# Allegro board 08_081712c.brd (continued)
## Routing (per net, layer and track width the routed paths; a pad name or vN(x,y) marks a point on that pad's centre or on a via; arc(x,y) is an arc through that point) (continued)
_N2537: length 3.2
  BOTTOM w0.305: R591.1 105.91,58.5 105.61,58.81 U77.4
_N2538: length 3.2
  BOTTOM w0.305: R592.1 97.91,59.31 U77.8
_N2539: length 3
  BOTTOM w0.305: U77.3 106.49,59.31 C416.1
_N2540: length 7.2
  BOTTOM w0.305: U77.6 100.38,56.81 R593.1 99.83,56.26 96.52,56.26 R594.1 95,56.13 C419.1
_N2565: length 3.5
  BOTTOM w0.305: C424.1 225.3,58.5 225.6,58.81 U78.7
_N2567: length 3.2
  BOTTOM w0.305: U78.4 232.61,58.81 232.91,58.5 R595.1
_N2568: length 3.2
  BOTTOM w0.305: U78.8 224.91,59.31 R596.1
_N2569: length 3
  BOTTOM w0.305: U78.3 233.49,59.31 C422.1
_N2570: length 7.2
  BOTTOM w0.305: U78.6 227.38,56.81 R597.1 226.83,56.26 223.52,56.26 R598.1 222,56.13 C425.1
_N2633: length 1
  BOTTOM w0.114: R599.1 208.5,23.57 v2(207.84,22.91)
_N2642: length 9.5
  BOTTOM w0.127: PB1.3 173.24,23.24 166.76,23.24 R9.1
_N2684: length 87.7
  TOP w0.127: v1(188.85,76.32) 190.23,76.32 191.34,75.21 191.34,66.9 183.97,59.54 183.97,28.14 165.89,10.06 v1(165.89,3.49)
  BOTTOM w0.127: R600.1 v1(188.85,76.32) ; PB1.5 v1(165.89,3.49)
_N2688: length 95.2
  TOP w0.127: v1(152.18,3.49) 158,3.49 183.04,28.53 183.04,59.59 190.91,67.46 190.91,74.7 v1(189.99,75.62)
  BOTTOM w0.127: PB2.5 v1(152.18,3.49) ; R601.1 v1(189.99,75.62)
_N2692: length 183.3
  TOP w0.127: v1(184.84,32.49) 184.84,59.33 192.96,67.46 192.96,74.5 v1(191.13,76.32) ; v1(234.19,16.74) 246.05,16.74 252.02,10.77 285.62,10.77 v1(292.89,3.49)
  L8_SIG w0.127: v1(234.19,16.74) 217.65,16.74 211.84,10.92 203.41,10.92 202.93,11.4 202.48,11.4 202,10.92 193.47,10.92 186.51,17.88 186.51,30.79 184.84,32.47 v1(184.84,32.49)
  BOTTOM w0.127: R602.1 v1(191.13,76.32) ; PB3.5 v1(292.89,3.49)
_N2696: length 169.2
  TOP w0.127: v1(279.18,3.49) 272.53,10.13 251.43,10.13 245.39,16.18 v1(235.08,16.18) ; v1(192.28,76.32) 192.28,76.32 193.77,74.83 193.77,67.12 185.64,59 v1(185.64,30.89)
  L8_SIG w0.127: v1(235.08,16.18) 218.11,16.18 212.24,10.31 193.29,10.31 185.64,17.96 v1(185.64,30.89)
  BOTTOM w0.127: R603.1 v1(192.28,76.32) ; PB4.5 v1(279.18,3.49)
_N2698: length 9.8
  BOTTOM w0.127: S14.3 248.64,25.51 C383.1 248.66,25.54 U64.1 244.33,25.54 244.03,25.84 R546.2
`: length 386.4
  TOP w0.14: J1.T1 27.3,14.9 R567.1 27.3,16.29 R566.2 v1(26.07,16.3) ; J2.T1 394.97,14.9 R572.1 394.96,16.29 R571.2 v1(393.74,16.3)
  L3_SIG w0.127: v1(26.07,16.3) 52.9,16.3 56.13,19.53 91.49,19.53 100.3,10.72 198.58,10.72 199.08,10.21 208.79,10.21 209.3,10.72 315.53,10.72 317.13,12.32 368.53,12.32 373.58,17.37 392.66,17.37 v1(393.74,16.3)
A0N_FB: length 15.6
  TOP w0.508: 328.85,146.94 329.56,146.23 R174.1 ; 328.85,146.94 U22.7 325.18,146.94 R170.2 323.24,146.62 C118.2 ; 328.85,146.94 329.56,147.65 329.56,152.26 S3.3
A1N_FB: length 15.6
  TOP w0.508: C120.2 304.19,146.62 R172.2 306.13,146.94 U23.7 309.8,146.94 ; 309.8,146.94 310.52,146.23 R176.1 ; 309.8,146.94 310.52,147.65 310.52,152.26 S4.3
A2B1_IO1: length 67.4
  TOP w0.127: DS7.A v1(24.51,105.12) 25.31,105.92 26.94,105.92 29.73,108.7 U8.14
  BOTTOM w0.127: J4.52 23.3,74.2 24.03,74.93 25.4,74.93 26.04,75.56 39.37,75.56 40.01,76.2 40.01,93.6 30.23,103.38 27.81,103.38 26.67,104.52 25.11,104.52 v1(24.51,105.12)
A2B1_IO2: length 64.7
  TOP w0.127: U8.15 30.23,108.5 26.85,105.12 v1(26.04,105.12) DS8.A
  BOTTOM w0.127: v1(26.04,105.12) 26.71,105.12 28.07,103.76 30.35,103.76 40.36,93.75 40.36,76.05 39.52,75.21 26.18,75.21 25.53,74.55 24.77,74.55 24.57,74.36 J4.48
A2B1_IO7: length 61.8
  TOP w0.127: DS9.A v1(27.56,105.12) 30.73,108.29 U8.16
  BOTTOM w0.127: J4.44 25.84,74.28 26.42,74.85 39.67,74.85 40.72,75.9 40.72,93.9 30.48,104.14 28.54,104.14 v1(27.56,105.12)
A2B1_IRQ: length 186.7
  TOP w0.127: SOMA.227 v1(170.65,64.78)
  BOTTOM w0.127: J4.60 20.76,62.83 49.13,34.47 103.61,34.47 126.77,57.63 164.44,57.63 170.65,63.84 v1(170.65,64.78)
A2B1_RESET: length 184.5
  TOP w0.127: SOMA.225 v1(170.14,64.27)
  BOTTOM w0.127: J4.56 22.03,62.24 49.25,35.03 103.58,35.03 126.54,57.99 163.86,57.99 v1(170.14,64.27)
A2B2_IO1: length 74.1
  TOP w0.127: U8.17 31.23,108.07 29.08,105.92 v1(29.08,105.12) DS10.A
  BOTTOM w0.127: J5.52 76.01,74.23 75.44,74.8 60.2,74.8 58.17,76.83 58.17,84.38 48.54,94 41.12,94 30.61,104.52 29.68,104.52 v1(29.08,105.12)
A2B2_IO2: length 73.6
  TOP w0.127: DS11.A v1(30.61,105.12) 30.61,106.55 31.73,107.68 U8.18
  BOTTOM w0.127: v1(30.61,105.12) 30.61,105.03 41.27,94.36 48.69,94.36 58.53,84.52 58.53,76.98 60.35,75.16 76.48,75.16 77.28,74.36 J5.48
A2B2_IO7: length 66.3
  TOP w0.127: DS12.A v1(32.13,105.12)
  BOTTOM w0.127: v1(32.13,105.12) 32.13,104.01 41.42,94.72 48.84,94.72 58.88,84.67 58.88,77.13 60.5,75.52 77.26,75.52 78.55,74.23 J5.44
A2B2_IRQ: length 111.4
  TOP w0.127: SOMA.233 v1(172.14,64.27)
  L8_SIG w0.127: v1(172.14,64.27) 172.14,63.28 169.57,60.71 126.06,60.71 121.36,65.41 112.4,65.41 111.99,65.81 77.57,65.81 76.71,66.67 74.12,66.67 v1(73.47,67.32)
  BOTTOM w0.127: J5.60 v1(73.47,67.32)
A2B2_RESET: length 109.2
  TOP w0.127: SOMA.231 v1(171.65,64.78)
  L8_SIG w0.127: v1(171.65,64.78) 171.65,63.49 169.23,61.07 126.4,61.07 121.64,65.83 112.68,65.83 112.34,66.17 78.11,66.17 76.95,67.32 v1(74.74,67.32)
  BOTTOM w0.127: J5.56 v1(74.74,67.32)
A2B3_IO1: length 127.1
  TOP w0.127: DS13.A v1(252.48,110.2) 253.28,111 254.91,111 257.69,113.78 U51.14
  L8_SIG w0.127: v1(338.65,75.69) 329.03,75.69 327.79,76.93 322.86,76.93 321.06,78.74 321.06,86.96 321.94,87.85 321.94,90.04 318.26,93.73 318.26,102.4 312.86,107.8 254.88,107.8 v1(252.48,110.2)
  BOTTOM w0.127: P3.52 v1(338.65,75.69)
A2B3_IO2: length 126.2
  TOP w0.127: U51.15 258.2,113.58 254.82,110.2 v1(254,110.2) DS14.A
  L8_SIG w0.127: v1(254,110.2) 256.02,108.18 312.98,108.18 318.64,102.52 318.64,93.85 323.47,89.03 323.47,82.3 322.07,80.9 322.07,78.49 323.27,77.29 327.94,77.29 328.92,76.31 339.3,76.31 v1(339.92,75.69)
  BOTTOM w0.127: P3.48 v1(339.92,75.69)
A2B3_IO7: length 121
  TOP w0.127: DS15.A v1(255.52,110.2) 258.69,113.37 U51.16
  L8_SIG w0.127: v1(341.19,75.69) 340.04,76.83 329.26,76.83 326.14,79.96 326.14,86.87 319,94.01 319,102.67 313.11,108.56 257.16,108.56 v1(255.52,110.2)
  BOTTOM w0.127: P3.44 v1(341.19,75.69)
A2B3_IRQ: length 55.4
  TOP w0.127: SOMB.227 297.65,64.35 296.98,63.69 v1(296.98,61.71)
  L8_SIG w0.127: v1(296.98,61.71) 317.3,61.71 318.74,60.27 332.43,60.27 335.92,63.75 335.92,70.99 336.11,71.18 v1(336.11,71.72)
  BOTTOM w0.14: P3.60 v1(336.11,71.72)
A2B3_RESET: length 57.5
  TOP w0.127: v1(296.43,61.14) 296.43,63.77 297.14,64.48 SOMB.225
  L8_SIG w0.127: v1(296.43,61.14) 317.37,61.14 318.59,59.91 332.78,59.91 336.55,63.68 336.55,70.9 v1(337.38,71.72)
  BOTTOM w0.14: P3.56 v1(337.38,71.72)
A2B4_IO1: length 170.6
  TOP w0.127: U51.17 259.2,113.15 257.05,111 v1(257.05,110.2) DS16.A
  L8_SIG w0.127: v1(391.35,75.64) 390.41,76.58 375.72,76.58 368.86,83.44 361.32,83.44 360.17,82.3 333.88,82.3 333.6,82.58 333.6,86.82 331.91,88.52 326,88.52 320.07,94.45 320.07,103.11 312.8,110.38 305.27,110.38 304.53,109.64 301.28,109.64 300.51,110.41 298.88,110.41 298.12,109.65 262.43,109.65 260.93,111.15 258,111.15 v1(257.05,110.2)
  BOTTOM w0.127: P4.52 v1(391.35,75.64)
A2B4_IO2: length 166.8
  TOP w0.127: U51.18 259.69,112.76 258.57,111.63 v1(258.57,110.2) DS17.A
  L8_SIG w0.127: v1(392.62,74.73) 391.49,74.73 390.15,76.07 375.39,76.07 370.56,80.9 360.93,80.9 360.11,81.72 332.04,81.72 331.06,82.7 331.06,86.82 330,87.88 326.13,87.88 319.71,94.31 319.71,102.96 313.39,109.28 262.3,109.28 262.27,109.31 261.89,109.31 260.45,110.74 259.12,110.74 v1(258.57,110.2)
  BOTTOM w0.127: P4.48 v1(392.62,74.73)
A2B4_IO7: length 158.9
  TOP w0.127: DS18.A v1(260.1,110.2)
  L8_SIG w0.127: v1(260.1,110.2) 261.38,108.92 313.25,108.92 319.35,102.81 319.35,94.16 326.03,87.48 327.87,87.48 328.68,86.67 328.68,82.17 329.48,81.37 359.83,81.37 362.71,78.49 372.06,78.49 374.98,75.56 389.89,75.56 391.27,74.18 393.51,74.18 v1(393.89,74.56)
  BOTTOM w0.127: P4.44 v1(393.89,74.56)
A2B4_IRQ: length 107.3
  TOP w0.127: SOMB.233 299.14,63.94 298.66,63.46 v1(298.66,60.59)
  L8_SIG w0.127: v1(388.81,71.72) 388.81,70.07 387.86,69.12 375.61,69.12 371.6,73.13 360.63,73.13 351.04,63.53 337.4,63.53 333.42,59.56 317.68,59.56 316.65,60.59 v1(298.66,60.59)
  BOTTOM w0.127: P4.60 v1(388.81,71.72)
A2B4_RESET: length 109.1
  TOP w0.127: SOMB.231 298.65,64.08 297.81,63.25 v1(297.81,60.05)
  L8_SIG w0.127: v1(297.81,60.05) 316.15,60.05 317.37,58.83 333.4,58.83 337.57,62.99 352.6,62.99 360.2,70.59 372.01,70.59 374.37,68.22 388.23,68.22 390.08,70.07 v1(390.08,71.72)
  BOTTOM w0.127: P4.56 v1(390.08,71.72)
A2N_FB: length 15.6
  TOP w0.508: S5.3 289.94,152.26 289.94,147.65 289.23,146.94 ; 289.23,146.94 289.94,146.23 R202.1 ; 289.23,146.94 U24.7 285.56,146.94 R198.2 283.61,146.62 C132.2
A3N_FB: length 15.6
  TOP w0.508: R204.1 270.89,146.23 270.18,146.94 ; C134.2 264.56,146.62 R200.2 266.51,146.94 U25.7 270.18,146.94 ; 270.18,146.94 270.89,147.65 270.89,152.26 S6.3
A4N_FB: length 15.6
  TOP w0.508: 251.13,146.94 251.84,147.65 251.84,152.26 S7.3 ; 251.13,146.94 U26.7 247.46,146.94 R226.2 245.51,146.62 C146.2 ; 251.13,146.94 251.84,146.23 R230.1
A5N_FB: length 15.6
  TOP w0.508: C148.2 226.46,146.62 R228.2 228.41,146.94 U27.7 232.08,146.94 ; R232.1 232.79,146.23 232.08,146.94 ; 232.08,146.94 232.79,147.65 232.79,152.26 S8.3
A6N_FB: length 15.6
  TOP w0.508: S9.3 212.22,152.26 212.22,147.65 211.5,146.94 ; C160.2 205.89,146.62 R254.2 207.83,146.94 U28.7 211.5,146.94 ; R258.1 212.22,146.23 211.5,146.94
A7N_FB: length 15.6
  TOP w0.508: 192.45,146.94 193.17,147.65 193.17,152.26 S10.3 ; 192.45,146.94 193.17,146.23 R260.1 ; 192.45,146.94 U29.7 188.78,146.94 R256.2 186.84,146.62 C162.2
ADAU1966A_RESET_SOM_A*: length 114
  TOP w0.127: U8.6 v1(29.23,117.32)
  L3_SIG w0.127: v1(29.23,117.32) 30.01,116.54 42.75,116.54 58.86,100.42 130.95,100.42 v1(133.21,98.16)
  BOTTOM w0.14: U39.10 v1(133.21,98.16)
ADAU1966A_RESET_SOM_B*: length 141.9
  TOP w0.127: U51.6 257.2,122.02 256.94,122.28 v1(256.46,122.28)
  L8_SIG w0.127: v1(256.46,122.28) 250.44,122.28 238.68,110.52 227.58,110.52 226.95,109.88 224.61,109.88 223.11,111.38 201.45,111.38 201.04,111.79 167.18,111.79 162.23,106.83 136.8,106.83 135.36,105.38 v1(133.83,105.38)
  BOTTOM w0.127: U39.11 133.5,97.66 133.83,97.99 v1(133.83,105.38)
ADAU1979_A_RESET_SOM_A*: length 310.2
  TOP w0.127: v1(308.09,101.35) 308.09,99.81 306.78,98.5 296.19,98.5 293.42,101.27 293.42,102.11 290.96,104.57 269.88,104.57 268.58,103.28 237.57,103.28 234.26,99.97 201.37,99.97 198.35,96.95 175.16,96.95 167.03,105.08 143.94,105.08 131.95,93.09 99.75,93.09 94.74,98.09 62.69,98.09 40.74,120.04 30.68,120.04 29.72,119.08 29.72,116.25 U8.5
  BOTTOM w0.14: U35.10 v1(308.09,101.35)
ADAU1979_A_RESET_SOM_B*: length 89.3
  TOP w0.127: v1(256.67,123.06) 257.34,123.06 257.69,122.71 U51.5
  L8_SIG w0.127: v1(306.34,101.85) 307.71,100.48 310.06,100.48 310.62,101.04 310.62,105 308.99,106.63 307.11,106.63 306.65,107.09 254.08,107.09 251.69,109.47 251.69,111.58 257.1,116.99 257.1,122.63 v1(256.67,123.06)
  BOTTOM w0.14: U35.11 v1(306.34,101.85)
ADAU1979_B_RESET_SOM_A*: length 215.3
  TOP w0.127: U8.4 v1(30.23,117.32)
  L3_SIG w0.127: v1(230.37,101.35) 227.02,104.7 202.11,104.7 194.44,97.04 135.37,97.04 131.48,100.93 59.47,100.93 42.82,117.58 31.26,117.58 31,117.32 v1(30.23,117.32)
  BOTTOM w0.14: U37.10 v1(230.37,101.35)
ADAU1979_B_RESET_SOM_B*: length 41.5
  TOP w0.127: U51.4 258.2,123.19 v1(257.84,123.55)
  BOTTOM w0.127: U37.11 230.58,101.85 231.14,102.41 231.14,103 231.9,103.76 231.9,105.41 232.92,106.43 232.92,107.16 249.3,123.55 v1(257.84,123.55)
ADAU_CLK: length 12.8
  TOP w0.14: v1(308.09,102.35) 307.59,101.86 307.59,100.97 306.71,100.08 305.94,100.08 305.56,100.46 305.56,106.17 306.32,106.93 R123.1
  BOTTOM w0.14: U35.12 v1(308.09,102.35)
ADAU_CLK2: length 11.8
  TOP w0.14: v1(230.37,102.35) 229.87,101.86 229.87,101.44 228.81,100.38 228.42,100.38 228.14,100.66 228.14,106.47 228.6,106.93 R582.1
  BOTTOM w0.14: U37.12 v1(230.37,102.35)
ADC1_BCLK: length 9
  TOP w0.14: U20.5 302.3,103.45 v1(301.7,102.85)
  BOTTOM w0.14: U34.4 v1(301.7,102.85)
ADC1_LRCLK: length 11.4
  TOP w0.14: v1(299.7,101.35) 300.74,102.39 300.74,105.54 301.9,106.7 U20.4
  BOTTOM w0.14: U34.7 v1(299.7,101.35)
ADC1_RESET*: length 12.2
  TOP w0.14: v1(306.34,100.85) 307.09,101.6 307.09,105.79 308.23,106.93 308.23,108.51 308.03,108.71 307.71,108.71 R124.1 307.47,109.47 307.85,109.86 U16.3
  BOTTOM w0.14: U35.9 v1(306.34,100.85)
ADC1_ROUTE: length 300.6
  TOP w0.127: U8.9 27.69,114.49 v1(26.67,115.51) R509.1
  L8_SIG w0.114: v1(303.66,104.35) v1(309.98,104.35)
  L8_SIG w0.127: v1(26.67,115.51) 29.28,112.9 36.58,112.9 37.21,112.27 58.55,112.27 67.49,103.32 126.93,103.32 127.51,102.74 136.02,102.74 138.94,105.66 162.79,105.66 165.84,108.71 251.1,108.71 253.4,106.42 294.95,106.42 295.99,105.38 302.11,105.38 303.14,104.35 v1(303.66,104.35)
  BOTTOM w0.127: R509.1 v1(26.67,115.51)
  BOTTOM w0.14: U34.1 v1(303.66,104.35) ; U35.1 v1(309.98,104.35)
ADC1_SDATAOUT1: length 11
  TOP w0.14: v1(298.06,102.35) 297.43,102.98 297.43,104.14 301.1,107.8 U20.2
  BOTTOM w0.14: U34.12 v1(298.06,102.35)
ADC1_SDATAOUT2: length 14.3
  TOP w0.14: v1(296.3,100.85) 298.72,100.85 298.96,101.09 298.96,104.78 301.5,107.32 U20.3
  BOTTOM w0.14: U34.9 v1(296.3,100.85)
ADC1_TWI_SCL: length 15.4
  TOP w0.14: U16.4 308.25,109.45 308.74,108.97 308.74,101.47 309.75,100.46 310.39,100.46 310.77,100.84 310.77,101.89 v1(311.74,102.85)
  BOTTOM w0.14: U35.4 v1(311.74,102.85)
ADC1_TWI_SDA: length 10.8
  TOP w0.14: U16.5 308.65,109.82 309.25,109.22 309.25,102.09 v1(309.98,101.35)
  BOTTOM w0.14: U35.7 v1(309.98,101.35)
ADC2_BCLK: length 9
  TOP w0.14: v1(223.98,102.85) 224.57,103.45 U21.5
  BOTTOM w0.14: U36.4 v1(223.98,102.85)
ADC2_LRCLK: length 11.4
  TOP w0.14: U21.4 224.17,106.7 223.01,105.54 223.01,102.39 v1(221.97,101.35)
  BOTTOM w0.14: U36.7 v1(221.97,101.35)
ADC2_RESET*: length 11.9
  TOP w0.14: U17.3 230.12,109.86 229.74,109.47 R125.1 229.99,108.71 230.01,108.71 230.35,108.37 230.35,106.78 229.36,105.79 229.36,101.6 v1(228.61,100.85)
  BOTTOM w0.14: U37.9 v1(228.61,100.85)
ADC2_ROUTE: length 231.7
  TOP w0.127: U8.10 27.05,113.99 v1(26.67,114.36) R510.1
  L8_SIG w0.114: v1(234.57,108.08) v1(226.06,108.08)
  L8_SIG w0.127: v1(226.06,108.08) 166.24,108.08 163.22,105.05 139.22,105.05 136.28,102.12 127.52,102.12 126.71,101.31 123.43,101.31 121.88,102.86 106.67,102.86 106.3,102.49 67.31,102.49 58.14,111.66 29.38,111.66 v1(26.67,114.36)
  BOTTOM w0.127: R510.1 v1(26.67,114.36)
  BOTTOM w0.14: v1(234.57,108.08) 233.43,106.93 233.43,106.17 232.29,105.04 232.29,104.64 232.58,104.35 U37.1 ; v1(226.06,108.08) 226.06,105.16 225.26,104.35 U36.1
ADC2_SDATAOUT1: length 10.9
  TOP w0.14: U21.2 223.37,107.8 219.86,104.29 219.86,102.88 220,102.74 v1(220.34,102.74)
  BOTTOM w0.14: U36.12 219.96,102.35 v1(220.34,102.74)
ADC2_SDATAOUT2: length 14.2
  TOP w0.14: v1(218.58,100.85) 220.77,100.85 221.23,101.32 221.23,104.78 223.77,107.32 U21.3
  BOTTOM w0.14: U36.9 v1(218.58,100.85)
ADC2_TWI_SCL: length 14.4
  TOP w0.14: v1(234.01,102.85) 233.04,101.89 233.04,101.47 232.46,100.88 232.06,100.88 231.01,101.93 231.01,108.97 230.52,109.45 U17.4
  BOTTOM w0.14: U37.4 v1(234.01,102.85)
ADC2_TWI_SDA: length 10.8
  TOP w0.14: U17.5 230.92,109.82 231.52,109.22 231.52,102.09 v1(232.26,101.35)
  BOTTOM w0.14: U37.7 v1(232.26,101.35)
ADC_CHANNEL_0: length 83.2
  L3_SIG w0.254: P16.12 284.93,179.58 281.69,179.58 280.8,180.47 280.8,183.01 271.4,192.41 245.74,192.41 228.09,174.75 222.4,174.75 P15.34
ADC_CHANNEL_1: length 75.7
  L3_SIG w0.254: P15.33 223.77,175.88 227.26,175.88 245.17,193.79 272.17,193.79 282.12,183.84 P16.23
ADC_CHANNEL_2: length 92.5
  L3_SIG w0.254: P15.24 217.76,181.73 216.04,181.73 214.88,182.88 212.85,182.88 211.58,181.61 211.58,178.69 216.92,173.36 229.23,173.36 233.3,177.42 245.62,177.42 255.27,187.07 273.56,187.07 277.98,182.64 P16.9
ADC_CHANNEL_3: length 92.6
  L3_SIG w0.254: P16.20 273.84,182.72 270.76,185.8 255.8,185.8 246.14,176.15 233.83,176.15 229.63,171.96 216.03,171.96 210.31,177.67 210.31,182.88 212.34,184.91 219.74,184.91 P15.23
ADC_CHANNEL_4: length 92.4
  L3_SIG w0.254: P16.6 269.7,182.29 267.59,184.4 256.47,184.4 246.56,174.5 234.06,174.5 230.12,170.56 215.01,170.56 208.53,177.04 208.53,183.9 210.95,186.31 216.09,186.31 P15.4
ADC_CHANNEL_5: length 94.9
  L3_SIG w0.254: P16.17 263.77,182.88 256.92,182.88 246.76,172.72 234.82,172.72 231.14,169.04 214.25,169.04 207.14,176.15 207.14,184.91 211.84,189.61 221.3,189.61 P15.3
ADC_CHANNEL_6: length 112.9
  L3_SIG w0.254: P16.3 261.42,176.21 252.09,166.88 238.76,166.88 230.29,158.41 198.72,158.41 194.82,162.31 194.82,176.4 196.98,178.56 196.98,184.15 195.2,185.93 188.23,185.93 P13.4
ADC_CHANNEL_7: length 106.6
  L3_SIG w0.254: P13.3 192.64,189.61 194.69,189.61 198.63,185.67 198.63,177.29 196.6,175.26 196.6,162.97 199.67,159.89 209.68,159.89 215.9,166.12 232.92,166.12 236.73,169.93 250.44,169.93 257.28,176.77 P16.14
AIN0N: length 121.2
  TOP w0.508: C115.P 324.87,163.44 324.87,163.45 R155.1 v1(324.87,164.33)
  L8_SIG w0.254: v1(324.87,164.33) 319.81,159.26 256.29,159.26 239.9,175.64 219.02,175.64 P15.35
AIN0N_BUFFERED: length 43.3
  TOP w0.254: R178.1 326.3,135.27 326.94,134.63 329.46,134.63 330.1,134 330.1,131.95 328.57,130.43 303.4,130.43 302.26,129.29 302.26,125.62 302.24,125.6 U18.33
  TOP w0.508: C122.N 326.26,136.18 R178.1
AIN0P: length 62.3
  TOP w0.508: v1(335.78,164.33) R153.1 335.79,163.57 C113.P
  L3_SIG w0.254: v1(335.78,164.33) 331.45,168.66 304.17,168.66 290.07,182.75 286.55,182.75 P16.24
AIN0P_BUFFERED: length 43.3
  TOP w0.254: U18.32 302.74,125.6 302.72,125.62 302.72,129.1 303.59,129.97 328.76,129.97 330.56,131.76 330.56,134 331.19,134.63 333.72,134.63 334.35,135.27 R177.1
  TOP w0.508: C121.N 334.39,136.18 R177.1
AIN1N: length 93.3
  TOP w0.508: C116.P 305.82,163.44 305.82,163.45 R156.1 v1(305.82,164.33)
  L8_SIG w0.254: v1(305.82,164.33) 302.39,160.89 256.94,160.89 239.77,178.06 P15.32
AIN1N_BUFFERED: length 25.3
  TOP w0.254: R180.1 307.25,135.27 307.89,134.63 310.41,134.63 311.05,134 311.05,132.88 310.25,132.08 303.01,132.08 301.26,130.33 301.26,125.62 301.24,125.6 U18.35
  TOP w0.508: R180.1 307.21,136.18 C124.N
AIN1P: length 46.2
  TOP w0.508: C114.P 316.74,163.57 R154.1 v1(316.73,164.33)
  L3_SIG w0.254: P16.10 280.74,175.82 290.32,166.24 314.81,166.24 v1(316.73,164.33)
AIN1P_BUFFERED: length 25.3
  TOP w0.254: R179.1 315.3,135.27 314.67,134.63 312.14,134.63 311.51,134 311.51,132.69 310.44,131.62 303.2,131.62 301.72,130.14 301.72,125.62 301.74,125.6 U18.34
  TOP w0.508: C123.N 315.34,136.18 R179.1
AIN2N: length 81.2
  TOP w0.508: v1(285.25,164.33) R183.1 285.25,163.45 285.24,163.44 C129.P
  L8_SIG w0.254: v1(285.25,164.33) 282.19,167.39 255.78,167.39 238,185.17 218.7,185.17 P15.25
AIN2N_BUFFERED: length 25.3
  TOP w0.254: U18.37 300.24,125.6 300.26,125.62 300.26,130.14 298.78,131.62 291.54,131.62 290.47,132.69 290.47,134 289.84,134.63 287.31,134.63 286.68,135.27 R206.1
  TOP w0.508: R206.1 286.64,136.18 C136.N
AIN2P: length 31.8
  TOP w0.508: C127.P 296.16,163.57 R181.1 v1(296.16,164.33)
  L3_SIG w0.254: P16.21 276.6,177.29 289.57,164.33 v1(296.16,164.33)
AIN2P_BUFFERED: length 25.3
  TOP w0.254: U18.36 300.74,125.6 300.72,125.62 300.72,130.33 298.97,132.08 291.73,132.08 290.93,132.88 290.93,134 291.57,134.63 294.09,134.63 294.73,135.27 R205.1
  TOP w0.508: C135.N 294.77,136.18 R205.1
AIN3N: length 52.9
  TOP w0.508: v1(266.2,164.33) R184.1 266.2,163.45 266.19,163.44 C130.P
  L8_SIG w0.254: P15.22 237.31,183.06 254.51,165.86 264.66,165.86 v1(266.2,164.33)
AIN3N_BUFFERED: length 43.3
  TOP w0.254: R208.1 267.63,135.27 268.26,134.63 270.79,134.63 271.42,134 271.42,131.76 273.22,129.97 298.39,129.97 299.26,129.1 299.26,125.62 299.24,125.6 U18.39
  TOP w0.508: C138.N 267.59,136.18 R208.1
AIN3P: length 18.9
  TOP w0.508: v1(277.11,164.33) R182.1 277.11,163.57 C128.P
  L3_SIG w0.254: v1(277.11,164.33) 272.46,168.97 P16.7
AIN3P_BUFFERED: length 43.3
  TOP w0.254: U18.38 299.74,125.6 299.72,125.62 299.72,129.29 298.58,130.43 273.41,130.43 271.88,131.95 271.88,134 272.52,134.63 275.04,134.63 275.68,135.27 R207.1
  TOP w0.508: C137.N 275.72,136.18 R207.1
AIN4N: length 56.4
  TOP w0.508: C143.P 247.14,163.44 247.15,163.45 R211.1 v1(247.15,164.33)
  L8_SIG w0.254: P15.5 211.96,184.68 211.96,176.28 214.63,173.61 237.87,173.61 v1(247.15,164.33)
AIN4N_BUFFERED: length 43.3
  TOP w0.254: R234.1 248.58,135.27 249.21,134.63 251.74,134.63 252.37,134 252.37,131.95 250.85,130.43 225.68,130.43 224.54,129.29 224.54,125.62 224.52,125.6 U19.33
  TOP w0.508: R234.1 248.54,136.18 C150.N
AIN4P: length 24.1
  TOP w0.508: C141.P 258.06,163.57 R209.1 v1(258.06,164.33)
  L3_SIG w0.254: v1(258.06,164.33) 268.32,174.59 P16.18
AIN4P_BUFFERED: length 43.3
  TOP w0.254: U19.32 225.02,125.6 224.99,125.62 224.99,129.1 225.87,129.97 251.04,129.97 252.83,131.76 252.83,134 253.47,134.63 255.99,134.63 256.63,135.27 R233.1
  TOP w0.508: R233.1 256.67,136.18 C149.N
AIN5N: length 53.4
  TOP w0.508: C144.P 228.09,163.44 228.1,163.45 R212.1 v1(228.1,164.33)
  L8_SIG w0.254: P15.2 223.67,189.74 213.99,189.74 210.44,186.18 210.44,175.01 213.99,171.45 220.98,171.45 v1(228.1,164.33)
AIN5N_BUFFERED: length 25.3
  TOP w0.254: R236.1 229.53,135.27 230.16,134.63 232.69,134.63 233.32,134 233.32,132.88 232.53,132.08 225.29,132.08 223.54,130.33 223.54,125.62 223.52,125.6 U19.35
  TOP w0.508: C152.N 229.49,136.18 R236.1
AIN5P: length 35.2
  TOP w0.508: v1(239.01,164.33) R210.1 239.01,163.57 C142.P
  L3_SIG w0.254: P16.4 264.18,176.17 253.49,165.48 240.16,165.48 v1(239.01,164.33)
AIN5P_BUFFERED: length 25.3
  TOP w0.254: R235.1 237.58,135.27 236.94,134.63 234.42,134.63 233.78,134 233.78,132.69 232.72,131.62 225.48,131.62 223.99,130.14 223.99,125.62 224.02,125.6 U19.34
  TOP w0.508: C151.N 237.62,136.18 R235.1
AIN6N: length 45.4
  TOP w0.508: C157.P 207.52,163.44 207.53,163.45 R239.1 v1(207.53,164.33)
  L8_SIG w0.254: v1(207.53,164.33) 200.53,171.32 200.53,183.64 194.44,189.74 185.27,189.74 P13.5
AIN6N_BUFFERED: length 25.3
  TOP w0.254: U19.37 222.52,125.6 222.54,125.62 222.54,130.14 221.06,131.62 213.81,131.62 212.75,132.69 212.75,134 212.12,134.63 209.59,134.63 208.95,135.27 R262.1
  TOP w0.508: R262.1 208.91,136.18 C164.N
AIN6P: length 56.1
  TOP w0.508: v1(218.43,164.33) R237.1 218.44,163.57 C155.P
  L3_SIG w0.254: P16.15 260.04,177.37 251.21,168.53 238.12,168.53 231.14,161.54 227.46,161.54 224.68,164.33 v1(218.43,164.33)
AIN6P_BUFFERED: length 25.3
  TOP w0.254: U19.36 223.02,125.6 222.99,125.62 222.99,130.33 221.25,132.08 214,132.08 213.21,132.88 213.21,134 213.84,134.63 216.37,134.63 217,135.27 R261.1
  TOP w0.508: R261.1 217.04,136.18 C163.N
AIN7N: length 33.1
  TOP w0.508: C158.P 188.47,163.44 188.48,163.45 R240.1 v1(188.48,164.33)
  L8_SIG w0.254: P13.2 198.63,183.03 198.63,174.48 v1(188.48,164.33)
AIN7N_BUFFERED: length 43.3
  TOP w0.254: U19.39 221.52,125.6 221.54,125.62 221.54,129.1 220.66,129.97 195.49,129.97 193.7,131.76 193.7,134 193.07,134.63 190.54,134.63 189.9,135.27 R264.1
  TOP w0.508: C166.N 189.86,136.18 R264.1
AIN7P: length 68
  TOP w0.508: C156.P 199.39,163.57 R238.1 v1(199.38,164.33)
  L3_SIG w0.254: v1(199.38,164.33) 202.54,161.16 208.41,161.16 215.01,167.77 232.28,167.77 235.84,171.32 248.98,171.32 P16.1
AIN7P_BUFFERED: length 43.3
  TOP w0.254: R263.1 197.95,135.27 197.32,134.63 194.79,134.63 194.16,134 194.16,131.95 195.68,130.43 220.85,130.43 221.99,129.29 221.99,125.62 222.02,125.6 U19.38
  TOP w0.508: C165.N 197.99,136.18 R263.1
AUDIO_VREF_ADC_1: length 118.2
  TOP w0.203: A1.1 v1(290.04,123) ; A1.4 v1(285.27,124.9)
  TOP w0.508: R165.1 v1(315.21,150.38) ; R159.1 v1(334.26,150.38) ; R162.1 v1(326.4,150.38) ; R187.1 v1(294.63,150.38) ; R168.1 v1(307.35,150.38) ; R193.1 v1(275.58,150.38) ; R190.1 v1(286.77,150.38) ; R196.1 v1(267.72,150.38)
  L8_SIG w0.254: v1(334.26,150.38) v1(326.4,150.38) v1(315.21,150.38) v1(307.35,150.38) v1(294.63,150.38) v1(286.77,150.38) v1(275.58,150.38) v1(267.72,150.38) 265.34,147.99 265.34,139.87 280.3,124.9 v1(285.27,124.9) 286.83,124.9 288.73,123 v1(290.04,123)
AUDIO_VREF_ADC_2: length 118.2
  TOP w0.203: A2.1 v1(212.32,123) ; A2.4 v1(207.54,124.9)
  TOP w0.508: R249.1 v1(197.86,150.38) ; R252.1 v1(190,150.38) ; R215.1 v1(256.53,150.38) ; R243.1 v1(216.91,150.38) ; R224.1 v1(229.62,150.38) ; R218.1 v1(248.67,150.38) ; R246.1 v1(209.05,150.38) ; R221.1 v1(237.48,150.38)
  L8_SIG w0.254: v1(212.32,123) 211.01,123 209.11,124.9 v1(207.54,124.9) 202.58,124.9 187.61,139.87 187.61,147.99 v1(190,150.38) v1(197.86,150.38) v1(209.05,150.38) v1(216.91,150.38) v1(229.62,150.38) v1(237.48,150.38) v1(248.67,150.38) v1(256.53,150.38)
BRD_PWR_EN: length 506.9
  TOP w0.305: R461.2 v1(367.88,168.91)
  L3_SIG w0.127: P33.1 333.91,87.48 321.66,87.48 312.63,78.45 309.17,78.45 308.48,79.13 308.48,82.93 308.53,82.98 308.53,83.03 312.93,87.42 312.93,104.45 309.55,107.82 306.07,107.82 302.77,104.52 302.77,100.47 301.61,99.31 243.81,99.31 236.58,106.55 229.36,106.55 228.98,106.93 217.17,106.93 215.39,105.16 202.06,105.16 194.3,97.39 135.52,97.39 129.66,103.25 57.91,103.25 38.73,122.43 26.67,122.43 17.53,113.28 17.53,88.52 P32.1
  L8_SIG w0.127: P33.1 367.88,119.21 v1(367.88,168.91)
CAN0_RX_SOM_A: length 88.2
  TOP w0.127: SOMA.178 v1(158.39,74.95)
  TOP w0.14: U41.3 v1(90.55,37.15)
  BOTTOM w0.127: v1(158.39,74.95) 158.39,71.76 146.08,59.44 125.6,59.44 104.01,37.85 91.25,37.85 v1(90.55,37.15)
CAN0_RX_SOM_B: length 89.4
  TOP w0.127: SOMB.178 v1(285.39,74.95)
  TOP w0.14: U43.3 v1(353.47,37.12)
  BOTTOM w0.127: v1(353.47,37.12) 353.47,38.33 346.96,44.83 338.2,44.83 319.53,63.5 319.53,67.06 313.44,73.15 287.19,73.15 v1(285.39,74.95)
CAN0_SILENT_SOM_A: length 3.7
  TOP w0.14: U41.4 89.27,35.77 R537.1 R536.2
CAN0_SILENT_SOM_B: length 3.7
  TOP w0.14: R544.2 R545.1 352.19,35.75 U43.4
CAN0_STBY_SOM_A: length 73
  TOP w0.127: SOMA.113 v1(142.15,64.27)
  TOP w0.14: R535.2 v1(86.73,38.73) R538.1 86.73,37.25 86.74,37.24 U41.6
  BOTTOM w0.127: v1(142.15,64.27) 142.15,61.98 140.7,60.53 124.65,60.53 103.41,39.29 88.82,39.29 88.27,38.73 v1(86.73,38.73)
CAN0_STBY_SOM_B: length 103.2
  TOP w0.127: SOMB.113 v1(269.15,64.27)
  TOP w0.14: U43.6 349.66,37.22 349.65,37.22 R553.1 v1(349.65,38.71) R543.2
  BOTTOM w0.127: v1(349.65,38.71) 346.73,35.79 336.58,35.79 335.03,37.34 335.03,44.2 320.68,58.55 295.15,58.55 290.58,63.12 270.3,63.12 v1(269.15,64.27)
CAN0_TX_SOM_A: length 91.3
  TOP w0.127: SOMA.176 v1(157.9,75.45)
  TOP w0.14: U41.5 v1(88.01,37.15)
  BOTTOM w0.127: v1(157.9,75.45) 157.9,71.74 145.95,59.79 125.27,59.79 103.81,38.34 89.2,38.34 v1(88.01,37.15)
CAN0_TX_SOM_B: length 89.6
  TOP w0.127: SOMB.176 v1(284.9,75.41)
  TOP w0.14: U43.5 v1(350.93,37.12)
  BOTTOM w0.127: v1(350.93,37.12) 350.93,40.18 346.84,44.27 338.05,44.27 319.02,63.3 319.02,67.06 313.28,72.8 286.88,72.8 284.9,74.78 v1(284.9,75.41)
CAN1_RX_SOM_A: length 105.5
  TOP w0.127: SOMA.184 v1(159.9,75.45)
  TOP w0.14: U42.3 v1(76.45,37.15)
  BOTTOM w0.127: v1(76.45,37.15) 77.69,35.92 92.35,35.92 93.37,36.93 104.39,36.93 126.24,58.78 146.28,58.78 159.9,72.39 v1(159.9,75.45)
CAN1_RX_SOM_B: length 75.4
  TOP w0.127: SOMB.184 v1(286.9,72.03)
  TOP w0.14: U44.3 v1(339.37,37.12)
  BOTTOM w0.127: v1(339.37,37.12) 339.37,42.21 318.64,62.94 318.64,66.93 313.16,72.41 287.28,72.41 v1(286.9,72.03)
CAN1_SILENT_SOM_A: length 3.7
  TOP w0.14: R540.2 R541.1 75.18,35.77 U42.4
CAN1_SILENT_SOM_B: length 3.7
  TOP w0.14: R555.2 R556.1 338.09,35.75 U44.4
CAN1_STBY_SOM_A: length 88.8
  TOP w0.127: SOMA.115 v1(142.64,64.78)
  TOP w0.14: U42.6 72.64,37.24 72.64,37.25 R542.1 v1(72.64,38.73) R539.2
  BOTTOM w0.127: v1(142.64,64.78) 142.64,61.77 141.07,60.2 125.03,60.2 103.62,38.79 88.98,38.79 87.69,37.5 86.09,37.5 84.86,38.73 v1(72.64,38.73)
CAN1_STBY_SOM_B: length 85.3
  TOP w0.127: SOMB.115 v1(269.64,64.78)
  TOP w0.14: U44.6 335.56,37.22 335.55,37.22 R557.1 v1(335.55,38.71) R554.2
  BOTTOM w0.127: v1(335.55,38.71) 335.55,44.43 320.93,59.05 295.4,59.05 290.91,63.55 270.87,63.55 v1(269.64,64.78)
CAN1_TX_SOM_A: length 106.5
  TOP w0.127: SOMA.182 v1(159.39,74.95)
  TOP w0.14: U42.5 v1(73.91,37.15)
  BOTTOM w0.127: v1(159.39,74.95) 159.39,72.29 146.21,59.11 125.86,59.11 104.19,37.43 93.16,37.43 92.15,36.42 78.01,36.42 76.81,37.62 74.38,37.62 v1(73.91,37.15)
CAN1_TX_SOM_B: length 75.1
  TOP w0.127: SOMB.182 v1(286.39,71.38)
  TOP w0.14: U44.5 v1(336.83,37.12)
  BOTTOM w0.127: v1(286.39,71.38) 287.02,71.38 287.66,72.01 313.04,72.01 318.13,66.91 318.13,62.64 336.83,43.94 v1(336.83,37.12)
CHANNEL_1: length 126.9
  TOP w0.305: P14.24A 81.01,184.99 82.44,183.57 82.44,181.4 83.82,180.01 83.82,176.85 91.63,169.04 167.89,169.04 183.39,184.53 185.88,184.53 P13.24
CHANNEL_2: length 131.5
  TOP w0.305: P13.23 188.14,181.36 186.18,181.36 182.63,177.8 179.2,177.8 168.91,167.51 87.69,167.51 78.23,176.97 78.23,179.9 76.86,181.27 P14.10A
CHANNEL_3: length 137.4
  TOP w0.305: P13.34 185.43,176.15 180.21,176.15 170.05,165.99 83.12,165.99 72.78,176.33 72.78,180.03 71.4,181.41 71.4,182.49 72.71,183.8 P14.21A
CHANNEL_4: length 144.4
  TOP w0.305: P14.7A 67.67,185.05 67.67,184.98 65.71,183.02 65.71,181.5 67.25,179.96 67.25,176.66 79.44,164.47 172.47,164.47 182.75,174.75 186.54,174.75 P13.33
CHANNEL_5: length 143.6
  TOP w0.305: P12.4 156.02,189.74 162.43,189.74 166.83,185.34 166.83,177.48 159.78,170.43 93.85,170.43 87,177.29 87,188.34 84.96,190.37 66,190.37 P14.18A
CHANNEL_6: length 138.3
  TOP w0.305: P12.3 165.23,182.18 165.23,178.82 158.37,171.96 95.25,171.96 88.77,178.44 88.77,188.98 86.23,191.52 62.1,191.52 60.25,189.66 P14.4A
CHANNEL_7: length 121.5
  TOP w0.305: P12.24 154,184.66 149.86,184.66 138.81,173.61 98.87,173.61 94.87,177.61 94.87,189.93 92.14,192.66 60.05,192.66 57.04,189.65 56.98,189.65 P14.15A
CHANNEL_8: length 133.3
  TOP w0.305: P14.1A 51.88,185.93 51.31,186.5 51.31,190.06 55.05,193.8 93.73,193.8 96.77,190.75 96.77,178.24 99.38,175.64 137.96,175.64 148.5,186.18 154.97,186.18 P12.23
CHANNEL_9: length 87.9
  BOTTOM w0.305: P12.34 153.56,176.02 148.46,176.02 138.87,185.61 116.59,185.61 107.44,176.47 82.42,176.47 81.01,177.88 P14.24B
CHANNEL_10: length 92.6
  BOTTOM w0.305: P12.33 154.66,174.62 147.57,174.62 137.6,184.59 117.35,184.59 107.63,174.88 81.09,174.88 77.74,178.23 77.74,178.29 P14.10B
CHANNEL_11: length 52.4
  BOTTOM w0.305: P14.21B 73.59,182.9 73.65,182.9 74.46,183.71 112.46,183.71 115.32,186.56 121.1,186.56 P11.4
CHANNEL_12: length 69.5
  BOTTOM w0.305: P14.7B 68.55,182.92 69.98,184.34 69.98,186.42 70.92,187.36 86.26,187.36 88.65,184.98 111.82,184.98 116.52,189.67 125.98,189.67 P11.3
CHANNEL_13: length 72.1
  BOTTOM w0.305: P14.18B 64.4,175.44 66.48,173.36 108.33,173.36 117.87,182.9 119.62,182.9 121.03,181.48 122.27,181.48 P11.24
CHANNEL_14: length 76.4
  BOTTOM w0.305: P11.23 123.24,179.96 121.28,179.96 119.38,178.05 115.19,178.05 108.97,171.83 63.18,171.83 60.25,174.76 P14.4B
CHANNEL_15: length 80.2
  BOTTOM w0.305: P14.15B 56.1,174.6 60.39,170.31 109.73,170.31 115.44,176.02 121.81,176.02 P11.34
CHANNEL_16: length 84.7
  BOTTOM w0.305: P14.1B 51.94,175.32 58.36,168.91 110.74,168.91 116.33,174.5 122.78,174.5 P11.33
DAC1N: length 23.5
  TOP w0.203: U33.51 122.24,121.99 125.86,118.37 125.86,113.94 128.91,110.9 130.1,110.9 130.79,111.58 R290.1
DAC1N_OUT: length 131
  TOP w0.508: C212.N 145.3,112.72 R298.1 v1(148.07,112.72)
  L3_SIG w0.254: v1(148.07,112.72) 152.15,116.79 152.15,143.13 139.45,155.83 105.16,155.83 95.95,165.04 92.39,165.04 81.03,176.4 81.03,179.96 79.63,181.36 79.63,183.16 P14.12A
DAC1P: length 23.6
  TOP w0.203: U33.50 121.97,121.34 125.21,118.1 125.21,113.48 128.42,110.26 130.08,110.26 130.79,109.55 R289.1
DAC1P_OUT: length 98.5
  TOP w0.508: v1(148.07,108.42) R297.1 145.3,108.42 C211.N
  L8_SIG w0.254: P13.25 181.41,183.06 179.96,181.61 179.96,176.02 143.51,139.57 143.51,112.97 v1(148.07,108.42)
DAC2N: length 17.9
  TOP w0.203: U33.53 125.02,123.29 128.81,119.5 130.07,119.5 130.79,120.22 R292.1
DAC2N_OUT: length 127.4
  TOP w0.508: C214.N 145.3,121.35 R300.1 v1(148.07,121.35)
  L3_SIG w0.254: v1(148.07,121.35) 150.62,123.91 150.62,142.24 138.56,154.31 97.66,154.31 75.56,176.4 75.56,180.09 76.84,181.36 76.84,183.26 78.24,184.67 P14.23A
DAC2P: length 17.8
  TOP w0.203: U33.52 124.75,122.64 128.55,118.85 130.12,118.85 130.79,118.19 R291.1
DAC2P_OUT: length 96.7
  TOP w0.508: C213.N 145.3,117.05 R299.1 v1(148.07,117.05)
  L8_SIG w0.254: v1(148.07,117.05) 151.26,120.24 151.26,138.68 186.56,173.99 192.66,173.99 197.1,178.44 197.1,181.86 195.91,183.06 P13.22
DAC3N: length 17.8
  TOP w0.203: R286.1 130.79,128.85 130.08,128.14 128.24,128.14 124.69,124.59 U33.55
DAC3N_OUT: length 118.7
  TOP w0.508: v1(148.07,129.99) R294.1 145.3,129.99 C208.N
  L3_SIG w0.254: P14.9A 74.09,181.41 72.64,179.96 72.64,170.56 90.42,152.78 136.65,152.78 149.38,140.06 149.38,131.3 v1(148.07,129.99)
DAC3P: length 17.8
  TOP w0.203: R285.1 130.79,126.82 130.1,127.51 128.52,127.51 124.96,123.94 U33.54
DAC3P_OUT: length 72.5
  TOP w0.508: C207.N 145.3,125.69 R293.1 v1(148.07,125.69)
  L8_SIG w0.254: v1(148.07,125.69) 145.54,128.21 145.54,138.76 P13.35
DAC4N: length 23.5
  TOP w0.203: R288.1 130.79,137.49 130.08,136.78 128.42,136.78 125.21,133.56 125.21,128.94 122.16,125.89 U33.57
DAC4N_OUT: length 118.7
  TOP w0.508: v1(148.07,138.63) R296.1 145.3,138.63 C210.N
  L3_SIG w0.254: P14.20A 69.94,184.62 68.58,183.26 68.58,181.23 67.18,179.83 67.18,166.37 82.3,151.26 135.44,151.26 v1(148.07,138.63)
DAC4P: length 23.4
  TOP w0.203: U33.56 122.43,125.24 125.86,128.67 125.86,133.1 128.91,136.14 130.1,136.14 130.79,135.46 R287.1
DAC4P_OUT: length 67.5
  TOP w0.508: C209.N 145.3,134.32 R295.1 v1(148.07,134.32)
  L8_SIG w0.254: P13.32 190.43,176.15 185.93,176.15 149.44,139.66 149.44,135.69 v1(148.07,134.32)
DAC5N: length 37.2
  TOP w0.203: R306.1 136.64,145.14 137.27,144.51 137.27,143.53 136,142.25 130.54,142.25 125.71,137.43 114.79,137.43 111.65,134.29 U33.65
DAC5N_OUT: length 99.2
  TOP w0.508: v1(135.51,162.42) R314.1 135.51,159.65 C228.N
  L3_SIG w0.254: v1(135.51,162.42) 130.44,157.35 106.93,157.35 102.87,161.42 102.87,163.45 87.12,179.2 87.12,188.72 85.22,190.63 66.93,190.63 65.79,189.48 P14.6A
DAC5P: length 37.3
  TOP w0.203: U33.64 112.3,134.02 115.06,136.78 125.98,136.78 130.81,141.61 136.27,141.61 138.05,143.38 138.05,144.51 138.67,145.14 R305.1
DAC5P_OUT: length 68.3
  TOP w0.508: v1(139.81,162.42) R313.1 139.81,159.65 C227.N
  L8_SIG w0.254: v1(139.81,162.42) 142.49,165.1 160.15,165.1 170.05,175.01 170.05,183.64 163.96,189.74 153.52,189.74 P12.5
DAC6N: length 30.8
  TOP w0.203: R308.1 128.01,145.14 128.65,144.49 128.65,143.76 124.98,140.1 114.41,140.1 110.35,136.04 U33.67
DAC6N_OUT: length 91.3
  TOP w0.508: C230.N 126.87,159.65 R316.1 v1(126.87,162.42)
  L3_SIG w0.254: P14.17A 64.63,191.77 86.49,191.77 88.9,189.36 88.9,180.21 106.3,162.81 106.3,160.02 107.44,158.88 123.33,158.88 v1(126.87,162.42)
DAC6P: length 30.8
  TOP w0.203: U33.66 111,135.77 114.68,139.45 125.22,139.45 129.41,143.64 129.41,144.51 130.04,145.14 R307.1
DAC6P_OUT: length 61.4
  TOP w0.508: v1(131.17,162.42) R315.1 131.17,159.65 C229.N
  L8_SIG w0.254: v1(131.17,162.42) 135.5,166.75 159.46,166.75 168.4,175.69 168.4,182.96 163.3,188.06 P12.2
DAC7N: length 24.5
  TOP w0.203: U33.69 109.05,137.78 113.78,142.51 118.86,142.51 120.02,143.67 120.02,144.49 119.37,145.14 R302.1
DAC7N_OUT: length 92.3
  TOP w0.508: v1(118.23,162.42) R310.1 118.23,159.65 C224.N
  L3_SIG w0.254: P14.3A 57.48,190.07 60.2,192.79 92.2,192.79 95.25,189.74 95.25,177.55 108.08,164.72 108.08,161.16 108.84,160.4 116.22,160.4 v1(118.23,162.42)
DAC7P: length 24.6
  TOP w0.203: U33.68 109.7,137.52 114.05,141.86 119.13,141.86 120.78,143.51 120.78,144.51 121.4,145.14 R301.1
DAC7P_OUT: length 74.5
  TOP w0.508: v1(122.54,162.42) R309.1 122.54,159.65 C223.N
  L8_SIG w0.254: v1(122.54,162.42) 128.52,168.4 158.78,168.4 166.75,176.37 166.75,182.27 163.73,185.29 155.33,185.29 P12.25
DAC8N: length 18.5
  TOP w0.203: R304.1 110.73,145.14 111.38,144.49 111.38,143.16 107.75,139.53 U33.71
DAC8N_OUT: length 82.7
  TOP w0.508: C226.N 109.6,159.65 R312.1 v1(109.6,162.42)
  L3_SIG w0.254: v1(109.6,162.42) 109.6,165.23 96.52,178.31 96.52,190.37 93.22,193.68 58.23,193.68 P14.14A
DAC8P: length 18.6
  TOP w0.203: R303.1 112.77,145.14 112.14,144.51 112.14,143 108.4,139.26 U33.70
DAC8P_OUT: length 70
  TOP w0.508: C225.N 113.9,159.65 R311.1 v1(113.9,162.42)
  L8_SIG w0.254: P12.22 163.81,183.06 165.23,181.64 165.23,177.01 158.15,169.93 121.41,169.93 v1(113.9,162.42)
DAC9N: length 18.6
  TOP w0.203: U33.73 106.45,139.27 102.72,143 102.72,144.51 102.1,145.14 R322.1
DAC9N_OUT: length 29.4
  TOP w0.508: C244.N 100.96,159.65 R330.1 v1(100.96,162.42)
  L3_SIG w0.254: P14.12B 82.4,177.32 92.84,166.88 96.51,166.88 v1(100.96,162.42)
DAC9P: length 18.5
  TOP w0.203: U33.72 107.1,139.54 103.48,143.16 103.48,144.49 104.13,145.14 R321.1
DAC9P_OUT: length 57.1
  TOP w0.508: C243.N 105.26,159.65 R329.1 v1(105.26,162.42)
  L8_SIG w0.254: v1(105.26,162.42) 116.58,173.74 148.77,173.74 P12.35
DAC10N: length 24.6
  TOP w0.203: U33.75 105.15,137.52 100.82,141.86 95.74,141.86 94.09,143.51 94.09,144.51 93.46,145.14 R324.1
DAC10N_OUT: length 28.2
  TOP w0.508: v1(92.33,162.42) R332.1 92.33,159.65 C246.N
  L3_SIG w0.254: P14.23B 78.24,176.5 v1(92.33,162.42)
DAC10P: length 24.5
  TOP w0.203: U33.74 105.8,137.79 101.09,142.51 96.01,142.51 94.85,143.67 94.85,144.49 95.49,145.14 R323.1
DAC10P_OUT: length 75.2
  TOP w0.508: C245.N 96.63,159.65 R331.1 v1(96.63,162.42)
  L8_SIG w0.254: v1(96.63,162.42) 99.03,160.02 105.16,160.02 117.09,171.96 154.49,171.96 P12.32
DAC11N: length 30.8
  TOP w0.203: R318.1 84.83,145.14 85.45,144.51 85.45,143.64 89.64,139.45 100.18,139.45 103.85,135.78 U33.77
DAC11N_OUT: length 23.5
  TOP w0.508: v1(83.69,162.42) R326.1 83.69,159.65 C240.N
  L3_SIG w0.254: P14.9B 74.09,172.02 v1(83.69,162.42)
DAC11P: length 30.8
  TOP w0.203: U33.76 104.5,136.05 100.45,140.1 89.9,140.1 86.21,143.78 86.21,144.49 86.86,145.14 R317.1
DAC11P_OUT: length 47.7
  TOP w0.508: v1(87.99,162.42) R325.1 87.99,159.65 C239.N
  L8_SIG w0.254: v1(87.99,162.42) 87.99,166.22 109.83,188.06 P11.5
DAC12N: length 37.3
  TOP w0.203: R320.1 76.19,145.14 76.81,144.51 76.81,143.38 78.59,141.61 84.05,141.61 88.88,136.78 99.8,136.78 102.55,134.03 U33.79
DAC12N_OUT: length 24.5
  TOP w0.508: v1(75.05,162.42) R328.1 75.05,159.65 C242.N
  L3_SIG w0.254: v1(75.05,162.42) 69.94,167.54 P14.20B
DAC12P: length 37.2
  TOP w0.203: R319.1 78.22,145.14 77.59,144.51 77.59,143.53 78.86,142.25 84.32,142.25 89.15,137.43 100.07,137.43 103.2,134.3 U33.78
DAC12P_OUT: length 65.4
  TOP w0.508: C241.N 79.36,159.65 R327.1 v1(79.36,162.42)
  L8_SIG w0.254: v1(79.36,162.42) 83.69,166.75 86.23,166.75 109.09,189.61 128.55,189.61 P11.2
DAC13N: length 23.4
  TOP w0.203: U33.5 93.73,125.24 90.3,128.67 90.3,133.1 87.25,136.14 86.05,136.14 85.37,135.46 R334.1
DAC13N_OUT: length 48.6
  TOP w0.508: C252.N 70.86,134.32 R338.1 v1(68.08,134.32)
  L3_SIG w0.254: P14.6B 65.79,136.62 v1(68.08,134.32)
DAC13P: length 23.5
  TOP w0.203: R333.1 85.37,137.49 86.08,136.78 87.73,136.78 90.95,133.56 90.95,128.94 94,125.89 U33.4
DAC13P_OUT: length 80.4
  TOP w0.508: C251.N 70.86,138.63 R337.1 v1(68.08,138.63)
  L8_SIG w0.254: P11.25 109.02,183.06 90.42,164.47 90.42,154.31 77.34,141.22 70.68,141.22 v1(68.08,138.63)
DAC14N: length 17.8
  TOP w0.203: R336.1 85.37,126.82 86.05,127.51 87.63,127.51 91.2,123.94 U33.7
DAC14N_OUT: length 61.8
  TOP w0.508: v1(68.08,125.69) R340.1 70.86,125.69 C254.N
  L3_SIG w0.254: P14.17B 61.63,132.14 v1(68.08,125.69)
DAC14P: length 17.8
  TOP w0.203: U33.6 91.47,124.59 87.91,128.14 86.08,128.14 85.37,128.85 R335.1
DAC14P_OUT: length 102.9
  TOP w0.508: v1(68.08,129.99) R339.1 70.86,129.99 C253.N
  L8_SIG w0.254: P11.22 126.61,185.29 109.22,185.29 89.28,165.35 89.28,155.7 76.58,143 67.82,143 65.53,140.72 65.53,132.54 v1(68.08,129.99)
DAC15N: length 17.8
  TOP w0.203: U33.9 91.4,122.64 87.61,118.85 86.03,118.85 85.37,118.19 R342.1
DAC15N_OUT: length 69.3
  TOP w0.508: v1(68.08,117.05) R346.1 70.86,117.05 C260.N
  L3_SIG w0.254: v1(68.08,117.05) 57.48,127.66 P14.3B
DAC15P: length 17.9
  TOP w0.203: R341.1 85.37,120.22 86.08,119.5 87.34,119.5 91.13,123.29 U33.8
DAC15P_OUT: length 90.6
  TOP w0.508: v1(68.08,121.35) R345.1 70.86,121.35 C259.N
  L8_SIG w0.254: v1(68.08,121.35) 71.12,124.39 71.12,128.57 91.44,148.89 91.44,163.58 105.93,178.06 P11.35
DAC16N: length 23.6
  TOP w0.203: U33.11 94.19,121.34 90.95,118.1 90.95,113.48 87.73,110.26 86.08,110.26 85.37,109.55 R344.1
DAC16N_OUT: length 82.5
  TOP w0.508: C262.N 70.86,108.42 R348.1 v1(68.08,108.42)
  L3_SIG w0.254: v1(68.08,108.42) 53.33,123.17 P14.14B
DAC16P: length 23.5
  TOP w0.203: U33.10 93.92,121.99 90.3,118.37 90.3,113.94 87.25,110.9 86.05,110.9 85.37,111.58 R343.1
DAC16P_OUT: length 105.5
  TOP w0.508: v1(68.08,112.72) R347.1 70.86,112.72 C261.N
  L8_SIG w0.254: P11.32 126.68,175.9 105.92,175.9 94.36,164.34 94.36,149.48 72.52,127.63 72.52,117.15 v1(68.08,112.72)
DAC_AUDIO_CLK: length 41.9
  TOP w0.127: R281.1 v1(95.89,114.87)
  TOP w0.14: v1(127.25,106.03) 127.25,105.64 126.64,105.03 U32.8
  L3_SIG w0.127: v1(127.25,106.03) 127.25,104.9 126.62,104.27 122.81,104.27 122.3,104.77 122.3,108.58 116.01,114.87 v1(95.89,114.87)
DAC_CLK: length 9.2
  TOP w0.127: v1(133.21,97.16) 132.53,97.84 128.68,97.84 127,99.52 R265.1
  BOTTOM w0.14: U39.12 v1(133.21,97.16)
DAC_DBCLK: length 9.1
  TOP w0.127: v1(114.29,102.23) 114.66,102.61 U30.2
  BOTTOM w0.127: U38.4 112.16,96.66 112.5,97 112.5,98.02 114.81,100.33 114.81,101.72 v1(114.29,102.23)
DAC_DLRCLK: length 7.1
  TOP w0.127: v1(114.29,101.47) 114.92,102.11 114.94,102.11 115.06,102.23 U30.3
  BOTTOM w0.127: U38.7 111.74,98.16 114.29,100.71 v1(114.29,101.47)
DAC_DSDATA1: length 5.8
  TOP w0.127: U30.4 115.46,102.2 v1(116.19,101.47)
  BOTTOM w0.127: v1(116.19,101.47) 116.19,99.52 115.34,98.66 U38.9
DAC_DSDATA2: length 7.5
  TOP w0.127: U30.5 115.86,102.58 v1(116.2,102.23)
  BOTTOM w0.127: U38.12 115.18,97.16 116.7,98.68 116.7,101.74 v1(116.2,102.23)
DAC_DSDATA3: length 9.7
  BOTTOM w0.127: U40.4 122.95,97.14 122.56,97.54 122.56,100.71 121.67,101.6 119.89,101.6 118.89,102.6 U31.2
DAC_DSDATA4: length 11.4
  BOTTOM w0.127: U40.7 122.93,95.64 122.15,96.41 122.15,100.48 121.43,101.2 119.72,101.2 118.49,102.43 U31.3
DAC_DSDATA5: length 11.7
  BOTTOM w0.127: U40.9 121.3,95.14 121.67,95.5 121.67,100.22 121.05,100.84 119.38,100.84 118.09,102.13 U31.4
DAC_DSDATA6: length 9.8
  BOTTOM w0.127: U40.12 120.9,96.64 121.27,97.01 121.27,100.06 120.88,100.44 119.21,100.44 117.69,101.96 U31.5
DAC_MCLKO: length 95.6
  TOP w0.127: v1(176.92,135.26) S16.6A S16.5A
  TOP w0.305: R577.1 v1(97.92,112.34)
  BOTTOM w0.127: v1(97.92,112.34) 99.74,110.52 143.41,110.52 168.15,135.26 v1(176.92,135.26)
DAC_RESET*: length 7.6
  TOP w0.114: R266.1 127.04,102.68 U32.5
  TOP w0.127: R266.1 v1(129,101.57)
  BOTTOM w0.127: v1(129,101.57) 129,101.12 131.46,98.66 U39.9
DAC_ROUTE: length 119.5
  TOP w0.127: v1(127.56,95.16) 126.49,96.23 126.49,98.17 126.02,98.64 v1(124.92,98.64) 118.93,98.64 115.46,95.16 v1(112.04,95.16) ; R511.1 v1(26.67,113.22) 26.94,113.49 U8.11
  L8_SIG w0.127: v1(112.04,95.16) 110.86,96.34 110.86,97.04 106.04,101.85 66.99,101.85 57.67,111.18 28.72,111.18 v1(26.67,113.22)
  BOTTOM w0.127: R511.1 v1(26.67,113.22)
  BOTTOM w0.14: U38.1 v1(112.04,95.16) ; U40.1 v1(124.92,98.64) ; U39.1 v1(127.56,95.16)
DAC_TWI_SCL: length 10.5
  TOP w0.127: U32.3 126.24,102.11 v1(125.98,101.85)
  BOTTOM w0.127: v1(125.98,101.85) 126.75,101.09 128.4,101.09 130.05,99.44 130.05,97.08 129.63,96.66 U39.4
DAC_TWI_SDA: length 9
  TOP w0.127: U32.2 125.84,102.6 v1(125.09,101.85)
  BOTTOM w0.127: U39.7 129.15,98.16 129.41,98.42 129.41,99.44 128.39,100.46 126.49,100.46 v1(125.09,101.85)
DAI0_PIN01_SOM_A: length 254.8
  TOP w0.127: SOMA.29 v1(121.15,63.6)
  L8_SIG w0.127: v1(121.15,63.6) 120.78,63.23 120.78,61.53 123.35,58.95 191.97,58.95 197.08,53.85 223.13,53.85 223.9,54.61 228.22,54.61 228.98,53.85 249.43,53.85 254.43,58.85 254.43,65.63 249.68,70.38 249.68,73.58 243.88,79.38 237.62,79.38 236.85,80.14 236.85,84.35 237.54,85.04 245.44,85.04 254.1,93.7 293.72,93.7 298.93,98.92 298.93,102.59 v1(299.7,103.35)
  BOTTOM w0.14: U34.3 v1(299.7,103.35)
DAI0_PIN01_SOM_B: length 112.1
  TOP w0.127: SOMB.29 v1(248.15,64.27)
  L8_SIG w0.127: v1(301.7,103.85) 301.2,104.36 295.88,104.36 288.87,97.35 251.34,97.35 242.94,88.95 237.04,88.95 236.51,88.42 235.41,88.42 234.88,87.9 234.88,86.57 232.16,83.85 232.16,79.85 234.92,77.09 241.76,77.09 246.99,71.86 246.99,66.32 248.15,65.16 v1(248.15,64.27)
  BOTTOM w0.14: U34.2 v1(301.7,103.85)
DAI0_PIN02_SOM_A: length 255
  TOP w0.127: SOMA.31 v1(121.64,64.16)
  L8_SIG w0.127: v1(121.64,64.16) 120.93,64.16 120.42,63.65 120.42,61.38 123.2,58.6 191.69,58.6 196.7,53.59 196.83,53.59 197.08,53.34 223.13,53.34 223.89,54.1 227.96,54.1 228.85,53.21 249.3,53.21 254.94,58.85 254.94,65.84 250.19,70.59 250.19,73.79 244.22,79.76 238.89,79.76 238.44,80.21 238.44,82.49 239.79,83.83 244.74,83.83 253.97,93.07 296.14,93.07 v1(302.39,99.31)
  BOTTOM w0.14: U34.6 301.88,101.85 302.39,101.35 v1(302.39,99.31)
DAI0_PIN02_SOM_B: length 110.8
  TOP w0.127: SOMB.31 v1(248.64,64.78)
  L8_SIG w0.127: v1(248.64,64.78) 248.64,65.43 247.35,66.73 247.35,72.21 242.08,77.47 235.24,77.47 232.71,80 232.71,83.87 235.23,86.39 235.23,87.75 235.55,88.07 236.66,88.07 237.13,88.54 243.24,88.54 251.55,96.85 289.08,96.85 296.13,103.9 300.26,103.9 300.41,103.76 300.41,103.06 v1(299.7,102.35)
  BOTTOM w0.14: U34.5 v1(299.7,102.35)
DAI0_PIN03_SOM_A: length 220.5
  TOP w0.127: SOMA.33 v1(122.15,61.94)
  L8_SIG w0.127: v1(122.15,61.94) 123.99,60.1 186.39,60.1 195.25,68.96 206.13,68.96 206.3,69.14 206.36,69.14 207.47,70.25 207.47,71.32 215.01,78.87 215.01,85.72 v1(227.84,98.55) ; 253.44,105.08 293.93,105.08 294.28,104.72 301.83,104.72 304.24,102.31 305.79,102.31 v1(306.34,102.85)
  L8_SIG w0.14: v1(232.28,107.47) 251.05,107.47 253.44,105.08
  BOTTOM w0.14: v1(232.28,107.47) 232.28,106.55 231.39,105.66 231.39,104.01 230.23,102.85 U37.13 228.33,102.85 227.84,102.36 v1(227.84,98.55) ; U35.13 v1(306.34,102.85)
DAI0_PIN03_SOM_B: length 151.8
  TOP w0.127: SOMB.33 v1(249.15,64.21)
  L3_SIG w0.127: v1(308.23,105.87) 307.54,105.19 307.54,101.04 305.27,98.77 243.5,98.77 236.07,106.2 230.83,106.2 v1(230.5,105.87) 230.5,104.17 231.34,103.33 231.34,99.52 230.13,98.31 v1(230.13,83.13)
  L8_SIG w0.127: v1(230.13,83.13) 230.13,81.27 234.7,76.71 241.55,76.71 246.63,71.63 246.63,64.71 247.84,63.5 249,63.5 249.15,63.65 v1(249.15,64.21)
  BOTTOM w0.14: v1(230.5,105.87) 230.89,105.49 230.89,104.12 230.12,103.35 U37.14 ; v1(308.23,105.87) 308.23,103.74 307.85,103.35 U35.14
DAI0_PIN04_SOM_A: length 251.7
  TOP w0.127: SOMA.35 122.64,63.07 v1(122.63,63.06)
  L8_SIG w0.127: v1(298.06,101.35) 298.06,98.81 293.57,94.32 253.91,94.32 245.01,85.42 237.29,85.42 236.47,84.6 236.47,80.01 237.49,78.99 243.33,78.99 249.17,73.15 249.17,69.98 254,65.15 254,64.69 254.05,64.64 254.05,63.9 254,63.85 254,59.06 249.3,54.36 229.49,54.36 228.03,55.81 224.59,55.81 223.16,54.38 197.05,54.38 192.12,59.31 123.5,59.31 121.24,61.56 121.24,62.31 121.99,63.06 v1(122.63,63.06)
  BOTTOM w0.14: U34.10 v1(298.06,101.35)
DAI0_PIN04_SOM_B: length 100.5
  TOP w0.127: SOMB.35 v1(249.64,64.78)
  L8_SIG w0.127: v1(249.64,64.78) 249.64,65.32 247.7,67.26 247.7,72.47 242.32,77.85 236.73,77.85 234.44,80.14 234.44,84.2 238.33,88.09 243.61,88.09 251.94,96.42 289.94,96.42 v1(295.38,101.85)
  BOTTOM w0.14: U34.11 v1(295.38,101.85)
DAI0_PIN05_SOM_A: length 253.1
  TOP w0.127: SOMA.37 v1(123.15,62.48)
  L8_SIG w0.127: v1(123.15,62.48) 121.92,62.48 121.6,62.16 121.6,61.71 123.65,59.66 192.14,59.66 192.27,59.66 197.2,54.74 222.63,54.74 224.28,56.39 228.35,56.39 229.87,54.86 249.15,54.86 253.59,59.31 253.59,63.95 253.69,64.04 253.69,64.5 253.59,64.59 253.59,64.8 248.54,69.85 248.54,72.9 242.82,78.61 237.11,78.61 235.2,80.52 235.2,83.84 237.14,85.78 244.68,85.78 253.95,95.05 292.51,95.05 297.15,99.69 297.15,102.34 v1(298.12,103.3)
  BOTTOM w0.14: v1(298.12,103.3) 297.67,102.85 U34.13
DAI0_PIN05_SOM_B: length 102.3
  TOP w0.127: SOMB.37 v1(250.15,64.27)
  L8_SIG w0.127: v1(296.21,102.87) 296.21,101.68 290.53,95.99 252.32,95.99 244.04,87.71 238.57,87.71 234.85,83.99 234.85,80.37 236.99,78.23 242.57,78.23 248.06,72.75 248.06,67.79 250.15,65.7 v1(250.15,64.27)
  BOTTOM w0.203: U34.14 296.7,103.35 v1(296.21,102.87)
DAI0_PIN06_SOM_A: length 127.4
  TOP w0.127: SOMA.39 v1(123.64,64.78)
  L8_SIG w0.127: v1(220.85,98.55) 214.05,91.74 214.05,79.04 213.83,78.83 213.83,78.79 206.76,71.72 206.76,70.54 206.06,69.85 194.51,69.85 190.68,66.01 124.88,66.01 v1(123.64,64.78)
  BOTTOM w0.14: U36.3 221.64,103.35 220.85,102.57 v1(220.85,98.55)
DAI0_PIN06_SOM_B: length 61.6
  TOP w0.127: SOMB.39 v1(250.64,64.78)
  L3_SIG w0.127: v1(229.38,83.13) 229.38,83.89 229.59,84.1 229.59,94.89 226.31,98.17 226.31,101.52 v1(223.98,103.85)
  L8_SIG w0.127: v1(250.64,64.78) 250.64,63.29 250.47,63.12 247.52,63.12 246.13,64.52 246.13,71.41 241.21,76.33 234.44,76.33 229.38,81.39 v1(229.38,83.13)
  BOTTOM w0.14: U36.2 v1(223.98,103.85)
DAI0_PIN07_SOM_A: length 127.5
  TOP w0.127: SOMA.41 v1(124.15,64.27)
  L8_SIG w0.127: v1(124.15,64.27) 125.41,65.53 190.96,65.53 194.89,69.47 205.1,69.47 205.13,69.49 206.21,69.49 207.11,70.4 207.11,71.48 214.48,78.84 214.48,88.37 v1(224.66,98.55)
  BOTTOM w0.14: v1(224.66,98.55) 224.66,101.35 224.16,101.85 U36.6
DAI0_PIN07_SOM_B: length 62.5
  TOP w0.127: SOMB.41 v1(251.15,64.27)
  L3_SIG w0.127: v1(228.72,83.13) 228.72,84.13 228.14,84.71 228.14,94.16 223.04,99.26 223.04,101.29 v1(221.97,102.35)
  L8_SIG w0.127: v1(251.15,64.27) 251.15,63.25 250.51,62.62 247.26,62.62 245.62,64.26 245.62,71.25 240.89,75.97 234.03,75.97 228.72,81.28 v1(228.72,83.13)
  BOTTOM w0.14: U36.5 v1(221.97,102.35)
DAI0_PIN08_SOM_A: length 121.5
  TOP w0.127: SOMA.43 v1(124.64,67.72)
  L8_SIG w0.127: v1(124.64,67.72) 125.02,67.36 125.72,66.66 190.66,66.66 195.48,71.48 206.01,71.48 213.47,78.94 213.47,93.97 v1(218.06,98.55)
  BOTTOM w0.14: v1(218.06,98.55) 218.06,101.21 218.2,101.35 U36.10
DAI0_PIN08_SOM_B: length 64
  TOP w0.127: SOMB.43 v1(251.64,64.78)
  L3_SIG w0.127: v1(228.06,83.13) 228.06,84.15 227.38,84.84 227.38,94.01 220.37,101.02 v1(220.37,101.85)
  L8_SIG w0.127: v1(228.06,83.13) 228.06,81.31 233.76,75.62 240.61,75.62 245.11,71.12 245.11,63.88 246.87,62.12 250.72,62.12 251.64,63.05 v1(251.64,64.78)
  BOTTOM w0.14: U36.11 v1(220.37,101.85)
